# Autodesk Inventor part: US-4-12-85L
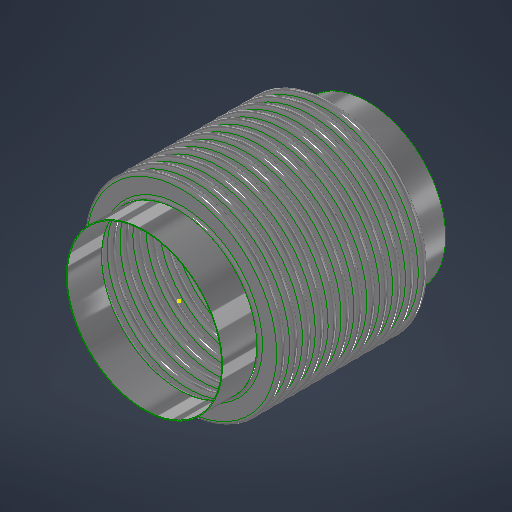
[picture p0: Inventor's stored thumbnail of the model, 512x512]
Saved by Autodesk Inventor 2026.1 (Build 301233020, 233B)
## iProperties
Category: 24 GA (0.024 THICK)
RuleStatus: InUse
Created: 2026-07
Part Number: US-4-12-85L
Project: =STOCK BELLOWS: <Stock Number><SFILL>
Material: ASTM A240-304
Description: =STOCK BELLOWS: <Stock Number>, <SID_> I.D., <SOD_> O.D., <SPLY_> PLY, <Category>, <SNET_CONS> CONS.<PITCH_><STANGENT_> TANGENT<SFILL>
Document SubType Name: Sheet Metal
Designer: LC
Stock Number: U.S-4-12-85L
Surface Area: 659.127 cm^2
Volume: 56.61 cm^3
Sheet Metal Rule: Default
Appearance: STAINLESS STEEL
NET_TUBE: 3.428
COUNTER: 1.500
PBAR: 1.214
PSET: 5.356
PLY: 2
CONS: 2
THK: 0.036
ID: 4.500
OD: 5.500
CONS_: 2
TANGENT: 0.500
PITCH: 0.375
BELLOWS_UPSET: 0.000
NET_CONS: 2
S_CONS: 0
Description_Units: 0
ID_M: 114.30 mm
OD_M: 139.70 mm
THK_M: 0.91 mm
ID_U: 4.500 in
OD_U: 5.500 in
THK_U: 0.036 in
TANGENT2: 0.500
d79: 1.000
d82: 1.000
d83: 26.000
d84: 24.000
d80: 2.571
d81: 10
SID: 2.375
SCONS_: 12
SPITCH: 0.250
SBELLOWS_UPSET: 0.000
SNET_CONS: 12
SS_CONS: 0
SCONS: 8
d174: 8
d177: 0.018
d178: 2.375
d179: 3.000
d180: 0.375
d181: 1.000
d182: 0.000
d190: 8
d191: 1
d192: 1
d193: 8
d194: 0
PART_NUMBER: U.S-4-12-85L
PRESSURE: 85
SIZE: 4.00
STANGENT_: 1.000
d214: 8
d217: 0.030
d218: 6.625
d219: 8.125
d220: 0.500
d221: 1.000
d222: 0.000
d230: 8
d231: 1
d232: 1
d233: 8
d234: 0
STANGENT: 4.000
SPLY_: 1
STHK_: 0.024
SID_: 4.500
SOD_: 5.750
SPITCH_: 0.375
STANGENT__: 1.000
SBELLOWS_UPSET_: 0.000
SDIFF_TAN: 1.000
TAN_TO_TAN: 0.750 in
d252: 2
d275: 2
d287: 0.050
d289: 0.500
d290: 0.000
d263: 2
d265: 1
d268: 2
d269: 0
d286: 2
d288: 1
d291: 2
d292: 0
SOD_NECK: 4 9/16
CFILL: .
SFILL: .
PITCH_: =, <SPITCH_> PITCH,
SREROLL: 0.750
MATTABLE: 20 GA (0.036 THICK)
MESH: ,
CSECT: 2
Author: LC
Keywords: 20 GA (0.036 THICK)
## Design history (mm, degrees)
sketch "Sketch2"
  geometry: L1 (0, -183.595)-(0, 600.956) reference; L2 (58.979, 0)-(57.15, 0); L3 (60.446, -1.467)-(66.554, -1.467); L4 (60.446, -3.296)-(66.554, -3.296); L5 (66.554, -8.058)-(60.446, -8.058); L6 (66.554, -6.229)-(60.446, -6.229); L7 (58.979, -9.525)-(57.15, -9.525); L8 (60.446, 0)-(60.446, -9.525); L9 (66.554, -4.762)-(69.85, -4.763); L10 (57.15, 0)-(57.15, -9.525); L11 (20.376, 102.841)-(20.376, 101.926); L12 (58.262, 488.877)-(58.262, 349.177); L13 (58.262, 479.352)-(58.262, 339.652); L14 (93.133, -58.817)-(93.133, -71.517); L15 (118.746, -66.401)-(118.746, -66.401); L16 (66.554, -6.229)-(66.554, -8.058); L17 (60.446, -6.229)-(60.446, -8.058); L18 (60.446, -7.144)-(66.554, -7.144); L19 (69.85, 0)-(69.85, -9.525); L20 (-66.554, -6.229)-(-66.554, -8.058); L21 (-66.554, -1.467)-(-60.446, -1.467); L22 (-66.554, -3.296)-(-60.446, -3.296); L23 (-60.446, -6.229)-(-66.554, -6.229); L24 (-66.554, -7.144)-(-60.446, -7.144); L25 (-60.446, -8.058)-(-66.554, -8.058); L26 (-60.446, -6.229)-(-60.446, -8.058); L27 (-57.15, -2.522)-(-57.15, -12.047); L28 (-60.446, -4.763)-(-57.15, -4.763); L29 (-66.554, 3.828)-(-66.554, -9.525); L30 (-68.021, 0)-(-69.85, 0); L31 (-69.85, 0)-(-69.85, -9.525); L32 (-68.021, -9.525)-(-69.85, -9.525); A1 r 1.467 centre (60.446, 0) between (58.979, 0) and (60.446, -1.467); A2 r 3.296 centre (60.446, 0) between (57.15, 0) and (60.446, -3.296); A3 r 3.296 centre (66.554, -4.762) between (66.554, -8.058) and (66.554, -1.467); A4 r 1.467 centre (66.554, -4.762) between (66.554, -6.229) and (66.554, -3.296); A5 r 1.467 centre (60.446, -9.525) between (60.446, -8.058) and (58.979, -9.525); A6 r 3.296 centre (60.446, -9.525) between (60.446, -6.229) and (57.15, -9.525); A7 r 2.381 centre (66.554, -4.762) between (66.554, -7.144) and (68.936, -4.762); A8 r 2.381 centre (60.446, -9.525) between (60.446, -7.144) and (58.064, -9.525); A9 r 1.467 centre (-66.554, -9.525) between (-66.554, -8.058) and (-68.021, -9.525); A10 r 1.467 centre (-60.446, -4.763) between (-60.446, -6.229) and (-60.446, -3.296); A11 r 2.381 centre (-60.446, -4.763) between (-60.446, -7.144) and (-58.064, -4.763); A12 r 3.296 centre (-60.446, -4.763) between (-60.446, -8.058) and (-60.446, -1.467); A13 r 2.381 centre (-66.554, -9.525) between (-66.554, -7.144) and (-68.936, -9.525); A14 r 3.296 centre (-66.554, -9.525) between (-66.554, -6.229) and (-69.85, -9.525); A15 r 1.467 centre (-66.554, 0) between (-68.021, 0) and (-66.554, -1.467); A16 r 3.296 centre (-66.554, 0) between (-69.85, 0) and (-66.554, -3.296); 10 further points
  constraints: 62 end point, 38 point on circle, 20 tangent, 16 centre point, 12 parallel, 9 midpoint, 7 vertical, 6 coincident, 6 concentric, 6 point on line, 4 equal radius, 4 perpendicular, 3 horizontal, 1 collinear, 1 horizontal alignment, 10 other
  dimensions: "THK" = 0.9144 distance of L11.start L11.end; "ID" = 114.3 distance of L11.end point (20.376, -12.374); "OD" = 139.7 distance of L12.start L12.end; "PITCH" = 9.525 distance of L12.start L13.start; "TANGENT" = 12.7 distance of L14.start L14.end; "BELLOWS_UPSET" = 0 distance of L15.start L15.end; "d43" = 114.3 diameter of L10 L1 (= ID); "d44" = 139.7 diameter of L9.end L1 (= OD); "d45" = 1.8288 distance between parallel lines of L5 L6 (computed from THK, PLY); "d46" = 3.29565 radius of A3 (computed from PITCH, THK, PLY); "UPSET_PITCH" = 9.525 distance of L2.end L7.end (derived); "SIDEWALL_ANGLE" = 0 deg angle of L3 L9 (derived); "CON_GAP" = 2.9337 distance of point (60.446, -6.229) point (60.446, -3.296) (derived); "TAN1" = 3.74046 dimension on A8 (derived); "TAN2" = 3.74046 dimension on A7 (derived); "LEG1" = 6.1087 distance of L18.start L18.end (derived); "d278" = 1.8288 distance between parallel lines of L25 L23 (derived); "d279" = 3.29565 radius of A12 (derived); "d280" = 9.525 distance of L30.end L31.end (derived); "d281" = 360 deg dimension on L21 L28 (derived); "d282" = 2.9337 distance of point (-66.554, -6.229) point (-66.554, -3.296) (derived); "d283" = 3.74046 dimension on A13 (derived); "d284" = 3.74046 dimension on A11 (derived); "d285" = 6.1087 distance of L24.start L24.end (derived); "d293" = 114.3 diameter of L27 L1 (derived); "d294" = 139.7 diameter of L31 L1 (derived)
  node "Sketch Rectangular Pattern1" dims "d31" = 25.4, "ID" = 114.3
  node "Sketch Rectangular Pattern2" dims "d39" = 25.4, "PITCH" = 9.525
revolve "CONS" stored, may be unused: angle "d48" = 90 deg
node "BELLOW MIDPLANE"
pattern_linear "Rectangular Pattern2" dims "d52" = 9.525 (= UPSET_PITCH)
sketch "Sketch5"
  geometry: C1 r 58.979 at (0, 0) reference; C2 r 57.15 at (0, 0) reference
extrude "TANGENT" new body sketch "Sketch5" distance "d53" = 12.7 (= TANGENT); taper "d54" = 0 deg
revolve "SAMETAN" stored, may be unused: angle "d65" = 90 deg
revolve "DIFFTAN" stored, may be unused: angle "d70" = 90 deg
sketch "Sketch9"
  geometry: L1 (58.391, 0)-(-58.391, 0) reference; L2 (0, -17.78)-(0, 17.78) reference; L3 (41.708, 0)-(-41.708, 0); L4 (41.708, -11.906)-(41.708, 11.906); L5 (29.008, -11.906)-(29.008, 11.906); L6 (15.418, 11.906)-(15.418, -11.906); L7 (-29.008, -11.906)-(-29.008, 11.906); L8 (-41.708, -11.906)-(-41.708, 11.906); L9 (40.914, -11.906)-(40.914, 11.906); L10 (41.708, -11.906)-(40.914, -11.906); L11 (41.708, 11.906)-(40.914, 11.906); L12 (15.815, 11.906)-(15.022, 11.906); L13 (15.022, 11.906)-(15.022, -11.906); L14 (15.022, -11.906)-(15.815, -11.906); L15 (15.815, -11.906)-(15.815, 11.906); L16 (-15.815, 11.906)-(-15.815, -11.906); L17 (-15.418, 11.906)-(-15.418, -11.906); L18 (-15.815, -11.906)-(-15.022, -11.906); L19 (-15.022, -11.906)-(-15.022, 11.906); L20 (-15.022, 11.906)-(-15.815, 11.906); L21 (-41.708, -11.906)-(-40.914, -11.906); L22 (-40.914, -11.906)-(-40.914, 11.906); L23 (-40.914, 11.906)-(-41.708, 11.906); L24 (-41.708, 11.906)-(-41.708, -11.906); L25 (41.708, -0.397)-(-41.708, -0.397); L26 (-41.708, -0.397)-(-41.708, 0.397); L27 (-41.708, 0.397)-(41.708, 0.397); L28 (41.708, 0.397)-(41.708, -0.397); L29 (-41.708, 11.906)-(41.708, 11.906); L30 (41.708, 11.906)-(41.708, 12.7); L31 (41.708, 12.7)-(-41.708, 12.7); L32 (-41.708, 12.7)-(-41.708, 11.906); L33 (41.708, -11.906)-(-41.708, -11.906); L34 (-41.708, -11.906)-(-41.708, -12.7); L35 (-41.708, -12.7)-(41.708, -12.7); L36 (41.708, -12.7)-(41.708, -11.906); 30 further points
  constraints: 68 end point, 13 midpoint, 13 parallel, 8 horizontal, 7 perpendicular, 6 equal length, 3 point on line, 2 vertical, 14 other
  dimensions: "d115" = 23.8125 distance of L4.start L4.end (derived); "d116" = 12.7 distance between parallel lines of L4 L5 (derived); "d117" = 13.58962 distance between parallel lines of L5 L6 (derived); "d125" = 44.42645 distance between parallel lines of L7 L6 (derived); "d127" = 12.7 distance between parallel lines of L8 L7 (derived); "d128" = 26.28962 distance between parallel lines of L6 L4 (derived); "d130" = 83.41607 distance between parallel lines of L8 L4 (derived); "RULER_THK" = 0.79375 distance between parallel lines of L4 L9; "d135" = 0.79375 distance of L13.end L14.end (derived); "d138" = 30.83684 distance of L13.end L16.end (derived); "d143" = 0.79375 distance of L22.end L8.end (derived); "d144" = 0.79375 distance between parallel lines of L27 L25 (derived)
extrude "RULER" join sketch "Sketch9" distance "d149" = 0.79375 (derived); taper "d150" = 0 deg
extrude "BARS" join sketch "Sketch9" distance "d151" = 0.79375 (derived); taper "d152" = 0 deg
pattern_linear "Rectangular Pattern4" dims "d155" = 30.83684 (derived)
sketch "Sketch13"
  geometry: L1 (93.149, -52.467)-(93.149, -77.867); L2 (57.76, 0)-(57.15, 0); L3 (57.76, -9.525)-(57.15, -9.525); L4 (70.339, -7.449)-(59.836, -7.449); L5 (70.339, -6.839)-(59.836, -6.839); L6 (70.339, -4.763)-(73.025, -4.763); L7 (59.836, -2.076)-(70.339, -2.076); L8 (59.836, 0)-(59.836, -9.525); L9 (57.15, 0)-(57.15, -9.525); L10 (58.254, -350.381)-(58.254, -496.431); L11 (58.254, -359.906)-(58.254, -505.956); L12 (58.254, -378.956)-(58.254, -525.006); L13 (58.254, -388.481)-(58.254, -534.531); L14 (58.254, -398.006)-(58.254, -544.056); L15 (58.254, -407.531)-(58.254, -553.581); L16 (58.254, -417.056)-(58.254, -563.106); L17 (58.254, -369.431)-(58.254, -515.481); L18 (20.376, 102.536)-(20.376, 101.926); L19 (59.836, -2.686)-(70.339, -2.686); L20 (0, -640.324)-(0, 226.168) reference; L21 (-23.752, 0)-(142.514, 0) reference; A1 r 2.076 centre (59.836, 0) between (57.76, 0) and (59.836, -2.076); A2 r 2.076 centre (59.836, -9.525) between (59.836, -7.449) and (57.76, -9.525); A3 r 2.686 centre (59.836, -9.525) between (59.836, -6.839) and (57.15, -9.525); A4 r 2.076 centre (70.339, -4.763) between (70.339, -6.839) and (70.339, -2.686); A5 r 2.686 centre (70.339, -4.763) between (70.339, -7.449) and (70.339, -2.076); A6 r 2.686 centre (59.836, 0) between (57.15, 0) and (59.836, -2.686); 6 further points; 1 other entity
  constraints: 38 end point, 15 point on circle, 9 tangent, 6 centre point, 6 parallel, 5 vertical alignment, 4 point on line, 4 vertical, 3 coincident, 3 concentric, 2 collinear, 2 equal radius, 1 horizontal, 1 perpendicular, 23 other
  dimensions: "SBELLOWS_UPSET_" = 0 distance of point (118.762, -66.401) point (118.762, -66.401); "STOTAL_THK_BELLOW__" = 0.6096 distance between parallel lines of L4 L5 (derived); "d224" = 2.68605 radius of A5 (derived); "d225" = 9.525 distance of L2.end L3.end (derived); "SSIDEWALL_ANGLE_" = 0 deg angle of L7 L6 (derived); "SSCON_GAP_" = 4.1529 distance of point (59.836, -6.839) point (59.836, -2.686) (derived); "d235" = 114.3 diameter of L9 L20 (derived); "d236" = 146.05 diameter of L6.end L20 (derived)
  node "Sketch Rectangular Pattern4" dims "d228" = 25.4
  node "Sketch Rectangular Pattern5" dims "d229" = 25.4
revolve "SBELLOW" stored, may be unused: angle "d197" = 90 deg
pattern_linear "Rectangular Pattern5" dims "d204" = 9.525 (derived)
revolve "STANGENT" stored, may be unused: angle "d240" = 90 deg
revolve "SSAMETAN" stored, may be unused: angle "d241" = 90 deg
revolve "SDIFFTAN" stored, may be unused: angle "d246" = 90 deg
revolve "INVCON" stored, may be unused: angle "d295" = 90 deg
pattern_linear "Rectangular Pattern6" dims "d298" = 9.525 (derived)
revolve "INVTANGENT" stored, may be unused: angle "d302" = 90 deg
revolve "INVSAMETAN" stored, may be unused: angle "d307" = 90 deg
revolve "INVDIFFTAN" stored, may be unused: angle "d312" = 90 deg
sketch "ID BELLOW MOUNT CALC"
  geometry: L1 (44.45, 0)-(38.1, 0); L2 (38.1, 0)-(38.1, 12.7); L3 (38.1, 12.7)-(44.45, 12.7); L4 (44.45, 12.7)-(44.45, 0); L5 (36.513, 12.7)-(34.684, 12.7); L6 (34.684, 12.7)-(34.684, 0); L7 (34.684, 0)-(36.513, 0); L8 (36.513, 0)-(36.513, 12.7); L9 (0, -2.54)-(0, 15.24) reference; L10 (-8.89, 0)-(53.34, 0) reference; 1 further point
  constraints: 16 end point, 5 parallel, 2 collinear, 2 horizontal, 2 perpendicular
  dimensions: "d314" = 12.7 distance of L5.end L6.end (derived); "d315" = 1.8288 distance of L5.start L5.end (derived); "IG" = 1.5875 distance between parallel lines of L2 L8; "PIPE_OD" = 88.9 diameter of L4 L9; "PIPE_WALL" = 6.35 distance of L2.end L3.end; "ID_MT_BELLOW" = 69.3674 diameter of L6 L9 (derived)
revolve "CFILL" stored, may be unused: angle "d320" = 90 deg
pattern_linear "Rectangular Pattern7" dims "d323" = 9.525 (derived)
revolve "SFILL" stored, may be unused: angle "d324" = 90 deg
pattern_linear "Rectangular Pattern8" dims "d327" = 9.525 (derived)
node "STOCK BELLOW MIDPLANE"
sketch "Sketch21"
  geometry: L1 (0, -100.013)-(0, 100.013) reference; L2 (-100.013, 0)-(100.013, 0) reference; L3 (-0.099, 71.437)-(0.099, 71.437); L4 (0.099, 71.437)-(0.099, 55.562); L5 (0.099, 55.562)-(-0.099, 55.562); L6 (-0.099, 55.562)-(-0.099, 71.437); C1 r 55.562 at (0, 0); C2 r 71.437 at (0, 0); 3 further points
  constraints: 8 end point, 2 centre point, 2 coincident, 2 parallel, 2 tangent, 1 horizontal, 1 perpendicular, 1 other
  dimensions: "d329" = 111.125 diameter of C1 (derived); "d330" = 142.875 diameter of C2 (derived); "d331" = 0.19844 distance of L3.start L3.end
extrude "CLAMSHELL" cut sketch "Sketch21" extent not by distance; stored distance "d332" = 0; taper "d333" = 0 deg
pattern_circular "Circular Pattern1" dims angle "d335" = 180 deg (derived)
node "BELLOW"
sketch "Sketch6"
  geometry: L1 (-19.05, 58.979)-(-6.35, 58.979); L2 (-6.35, 58.979)-(-6.35, 57.15); L3 (-6.35, 57.15)-(-19.05, 57.15); L4 (-19.05, 57.15)-(-19.05, 58.979); L5 (2.54, 0)-(-59.69, 0) reference; L6 (-38.1, -108.388)-(-38.1, 156.601) reference; 1 further point
  constraints: 8 end point, 2 parallel, 1 horizontal, 1 perpendicular
  dimensions: "d61" = 12.7 distance of L2.end L3.end (derived); "d62" = 1.8288 distance of L1.end L2.end (derived); "d63" = 114.3 diameter of L3 L5 (derived); "d64" = 19.05 distance between parallel lines of L4 L6 (derived)
sketch "Sketch12"
  geometry: 1 further point
sketch "Sketch14"
  geometry: L1 (-25.4, 57.76)-(0, 57.76); L2 (0, 57.76)-(0, 57.15); L3 (0, 57.15)-(-25.4, 57.15); L4 (-25.4, 57.15)-(-25.4, 57.76); L5 (5.08, 0)-(-30.48, 0) reference; L6 (0, -8.89)-(0, 53.34) reference; 1 further point
  constraints: 8 end point, 2 parallel, 1 collinear, 1 horizontal, 1 perpendicular
  dimensions: "d237" = 0.6096 distance of L3.end L1.start (derived); "d238" = 114.3 diameter of L3 L5 (derived); "d239" = 25.4 distance of L1.start L1.end (derived); "SOD_NECK" = 115.5192 diameter of L1 L5 (derived)
sketch "Sketch15"
  geometry: L1 (-8.89, 0)-(53.34, 0) reference; L2 (57.15, -114.3)-(57.76, -114.3); L3 (57.76, -114.3)-(57.76, -139.7); L4 (57.76, -139.7)-(57.15, -139.7); L5 (57.15, -139.7)-(57.15, -114.3); L6 (0, -170.18)-(0, 43.18) reference; 1 further point
  constraints: 8 end point, 2 parallel, 1 horizontal, 1 perpendicular
  dimensions: "d205" = 25.4 distance of L4.end L2.start (derived); "d206" = 0.6096 distance of L3.end L4.end (derived); "d207" = 114.3 diameter of L5 L6 (derived); "d208" = 114.3 distance between parallel lines of L1 L2 (derived)
node "TANGENT_"
node "SAME_TAN"
sketch "Sketch8"
  geometry: L1 (58.979, -19.05)-(57.15, -19.05); L2 (57.15, -19.05)-(57.15, -31.75); L3 (57.15, -31.75)-(58.979, -31.75); L4 (58.979, -31.75)-(58.979, -19.05); L5 (0, -40.64)-(0, 21.59) reference; L6 (-108.388, 0)-(156.601, 0) reference; 1 further point
  constraints: 8 end point, 2 parallel, 1 horizontal, 1 perpendicular
  dimensions: "d66" = 114.3 diameter of L2 L5 (derived); "TOTAL_THK_BELLOW" = 1.8288 distance of L2.end L3.end (derived); "d68" = 19.05 distance between parallel lines of L1 L6 (derived); "d69" = 12.7 distance of L1.end L2.end (derived)
node "DIFF_TAN"
node "Sketch Rectangular Pattern3" dims "d138" = 30.83684 (derived), "d141" = 25.4
node "SBELLOW_"
node "STANGENT_"
node "SSAME_TAN"
sketch "Sketch16"
  geometry: L1 (57.76, -114.3)-(57.15, -114.3); L2 (57.15, -114.3)-(57.15, -139.7); L3 (57.15, -139.7)-(57.76, -139.7); L4 (57.76, -139.7)-(57.76, -114.3); L5 (0, -170.18)-(0, 43.18) reference; L6 (-8.89, 0)-(53.34, 0) reference; 1 further point
  constraints: 8 end point, 2 parallel, 1 horizontal, 1 perpendicular
  dimensions: "SDIFF_TAN" = 25.4 distance of L3.end L1.start; "d243" = 0.6096 distance of L2.end L3.end (derived); "d244" = 114.3 distance between parallel lines of L1 L6 (derived); "d245" = 114.3 diameter of L2 L5 (derived)
node "SDIFF_TAN"
body "Solid15"
sketch "Sketch17"
  geometry: L1 (69.85, 12.7)-(68.021, 12.7); L2 (68.021, 12.7)-(68.021, 0); L3 (68.021, 0)-(69.85, 0); L4 (69.85, 0)-(69.85, 12.7); L5 (0, -2.54)-(0, 15.24) reference; L6 (-13.97, 0)-(83.82, 0) reference; 2 further points
  constraints: 8 end point, 2 parallel, 1 horizontal, 1 midpoint, 1 perpendicular, 1 point on line
  dimensions: "INVTANGENT" = 12.7 distance of L3.end L1.start (derived); "d300" = 1.8288 distance of L1.start L1.end (derived); "d301" = 139.7 diameter of L4 L5 (derived)
body "Solid16"
sketch "Sketch18"
  geometry: L1 (69.85, -19.05)-(68.021, -19.05); L2 (68.021, -19.05)-(68.021, -31.75); L3 (68.021, -31.75)-(69.85, -31.75); L4 (69.85, -31.75)-(69.85, -19.05); L5 (-13.97, 0)-(83.82, 0) reference; L6 (0, -40.64)-(0, 21.59) reference; 1 further point
  constraints: 8 end point, 2 parallel, 1 horizontal, 1 perpendicular
  dimensions: "d303" = 19.05 distance between parallel lines of L1 L5 (derived); "d304" = 12.7 distance of L3.end L1.start (derived); "d305" = 1.8288 distance of L2.end L3.end (derived); "d306" = 139.7 diameter of L4 L6 (derived)
body "Solid17"
sketch "Sketch19"
  geometry: L1 (69.85, -19.05)-(68.021, -19.05); L2 (68.021, -19.05)-(68.021, -31.75); L3 (68.021, -31.75)-(69.85, -31.75); L4 (69.85, -31.75)-(69.85, -19.05); L5 (0, -40.64)-(0, 21.59) reference; L6 (-13.97, 0)-(83.82, 0) reference; 1 further point
  constraints: 8 end point, 2 parallel, 1 horizontal, 1 perpendicular
  dimensions: "d308" = 12.7 distance of L1.end L2.end (derived); "d309" = 139.7 diameter of L4 L5 (derived); "d310" = 1.8288 distance of L2.end L3.end (derived); "d311" = 19.05 distance between parallel lines of L1 L6 (derived)
body "Solid18"
body "Solid19"
body "Solid20"
other parameters: "BMPL" = -57.15, "PSET" = 136.0424 (computed from OD, THK, PLY) [user parameter], "PBAR" = 30.83684 (= 0.570796 x PITCH + OD - ID) [user parameter; used in 1 equation term], "COUNTER" = 15 [user parameter], "NET_TUBE" = 87.07367 (computed from CONS_, PBAR, TANGENT) [user parameter], "S_CONS" = 0 [user parameter; used in 1 equation term], "ID_M" = 114.3 (= ID) [user parameter], "OD_M" = 139.7 (= OD) [user parameter], "THK_M" = 0.9144 (= THK) [user parameter], "ID_U" = 114.3 (= ID) [user parameter], "OD_U" = 139.7 (= OD) [user parameter], "THK_U" = 0.9144 (= THK) [user parameter], "D_UNITS" = 0 [user parameter], "TANGENT2" = 12.7 [user parameter], "TAN_TO_TAN" = 19.05 [user parameter], "OD_NECK" = 117.9576 [user parameter], "d79" = 25.4, "d80" = 65.29823 [user parameter], "d82" = 25.4, "d83" = 660.4, "d84" = 609.6, "sa_0" = 4, "FRAME_THK" = 0.79375 [user parameter], "CON_FLAT" = 13.58962 [user parameter], "SID" = 60.325 [user parameter], "SPITCH" = 6.35 [user parameter], "STANGENT_" = 25.4 [user parameter], "SBELLOWS_UPSET" = 0 [user parameter], "SS_CONS" = 0 [user parameter], "STAN_TO_TAN_" = 114.3 [user parameter], "d100" = 0.6096 [user parameter], "d191" = 25.4 [user parameter], "d194" = 0 [user parameter], "STANGENT" = 101.6 [user parameter], "d234" = 0 [user parameter], "SUPSET_PITCH_" = 9.525 [user parameter], "d269" = 0 [user parameter], "d287" = 1.27, "d289" = 12.7, "d290" = 0, "d292" = 0 [user parameter], "Thickness" = 3.048 (derived), "KFactor" = 4.4, "BendRadius" = 3.048 (derived), "BendReliefWidth" = 3.048 (derived), "BendReliefDepth" = 1.524 (derived), "CornerReliefSize" = 12.192 (derived), "SeamGap" = 0.00508, "MinimumRemnant" = 6.096 (derived), "TransitionRadius" = 3.048 (derived), "JacobiRadiusSize" = 3.048 (derived), "GapSize" = 3.048 (derived), "SREROLL" = 19.05 [user parameter], "CUR_STK_PITCH" = 9.525 [user parameter], "d328" = -57.15 (derived), "CSECTDEG" = 180 deg [user parameter]
